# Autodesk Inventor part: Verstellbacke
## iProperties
Created: 2008-02
Part Number: Verstellbacke
Document SubType Name: Modeling
Designer: Benno
Manufacturer: Standard
Standards Organization: Custom
Author: Benno
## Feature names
1. Extrusion1
2. Extrusion2
3. Fase1 [Chamfer]
